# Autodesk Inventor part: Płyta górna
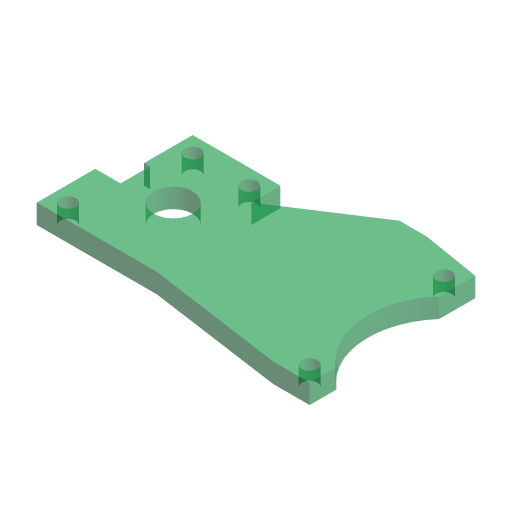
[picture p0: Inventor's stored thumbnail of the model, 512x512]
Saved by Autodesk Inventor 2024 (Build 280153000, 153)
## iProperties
Company: ATC
Shininess: 20.0
Angle Display Precision: 2
Document Length Units: 11269
Document Angle Units: 11279
Document Time Units: 11290
Document Mass Units: 11283
Document Length Units Precision: 3
Document Angle Units Precision: 2
Created: 2023-03
Part Number: Płyta górna
Material: Kurs-AJ
Document SubType Name: Modelowanie
Designer: Andrzej Jaskulski
Density: 1 g/cm^3
Stock Number: Płyta górna
Mass: 992.265 g
Surface Area: 266.604 cm^2
Volume: 99.2265 cm^3
Appearance: Przezroczyste - zielone 1
Checked By: A.J.
Engr Approved By: Andrzej Jaskulski
Mfg Approved By: Andrzej Jaskulski
Authority: A.J.
Density: 0.0
Volumn: 0.0
Area: 0.0
PropertySet Name: Model Information
Control State: 0
Master: False
Checked Out: False
Title: A.J.: Kurs R2024-MEP
Author: Andrzej Jaskulski
Revision Number: 1/24
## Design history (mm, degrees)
node "Bryła1"
node "Początek"
  node "Płaszczyzna YZ"
  node "Płaszczyzna XZ"
  node "Płaszczyzna XY"
  node "Oś X"
  node "Oś Y"
  node "Oś Z"
sketch "Szkic1"
  geometry: L1 (60, 60)-(60, 90); L2 (60, 90)-(73, 90) reference; L3 (73, 90)-(73, 105) reference; L4 (73, 105)-(70, 105) reference; L5 (70, 105)-(70, 130) reference; L6 (70, 130)-(115, 130) reference; L7 (115, 130)-(115, 115); L8 (115, 115)-(161.127, 144.955); L9 (161.127, 144.955)-(175, 144.955); L10 (175, 144.955)-(205, 139.955); L11 (205, 139.955)-(205, 121.458); L12 (60, 60)-(121.629, 60) reference; L13 (121.629, 60)-(191.251, 50) reference; L14 (191.251, 50)-(210, 50) reference; L15 (210, 50)-(210, 63.775) reference; L16 (95, 95)-(235, 95); C1 r 10 at (95, 95); C2 r 4 at (68, 68); C3 r 4 at (78, 122); C4 r 4 at (197, 131.955); C5 r 4 at (202, 58); C6 r 4 at (107, 122); A1 r 40 centre (235, 95) between (205, 121.458) and (210, 63.775)
  constraints: 32 end point, 7 centre point, 5 horizontal, 4 vertical, 2 point on circle, 1 coincident, 1 horizontal alignment, 1 perpendicular, 1 other
  dimensions: "d0" = 20 diameter of C1; "d5" = 10 distance between parallel lines of L5 L1; "d6" = 8 diameter of C3; "d7" = 8 diameter of C6 (= d6); "d8" = 8 diameter of C2 (= d6); "d9" = 8 diameter of C4 (= d6); "d10" = 8 diameter of C5 (= d6); "d11" = 8 distance from line of L6 C3.centre; "d12" = 8 distance from line of C3.centre L5 (= d11); "d13" = 8 distance from line of C6.centre L7 (= d11); "d14" = 8 distance from line of C2.centre L12 (= d11); "d15" = 8 distance from line of C2.centre L1 (= d11); "d16" = 8 distance from line of C4.centre L11 (derived); "d17" = 8 horizontal distance of C4.centre L10.end (= d11); "d18" = 8 distance from line of C5.centre L14 (= d11); "d19" = 8 distance from line of L15 C5.centre (= d11); "d20" = 35 distance from line of L12 L16.start; "d21" = 35 distance from line of L1 L16.start (= d20); "d22" = 40 radius of A1; "d25" = 140 distance of L16.start L16.end; "d26" = 135 distance between parallel lines of L11 L5; "d27" = 30 distance from line of L9.end L11; "d28" = 13 distance from line of L9 C4.centre; "d29" = 5 vertical distance of L10.end L9.end; "d30" = 90 horizontal distance of C4.centre C6.centre; "d32" = 60 distance from line of L9.end L7; "d33" = 15 distance of L6.end L7.end; "d34" = 57 deg angle of L7 L8; "d35" = 55 distance of L7.end L8.end
extrude "Wyciągnięcie proste1" new body sketch "Szkic1" distance "d1" = 10; taper "d2" = 0 deg
node "Korpusy bryłowe"
node "Korpusy powierzchniowe"
node "Punkt środkowy"
